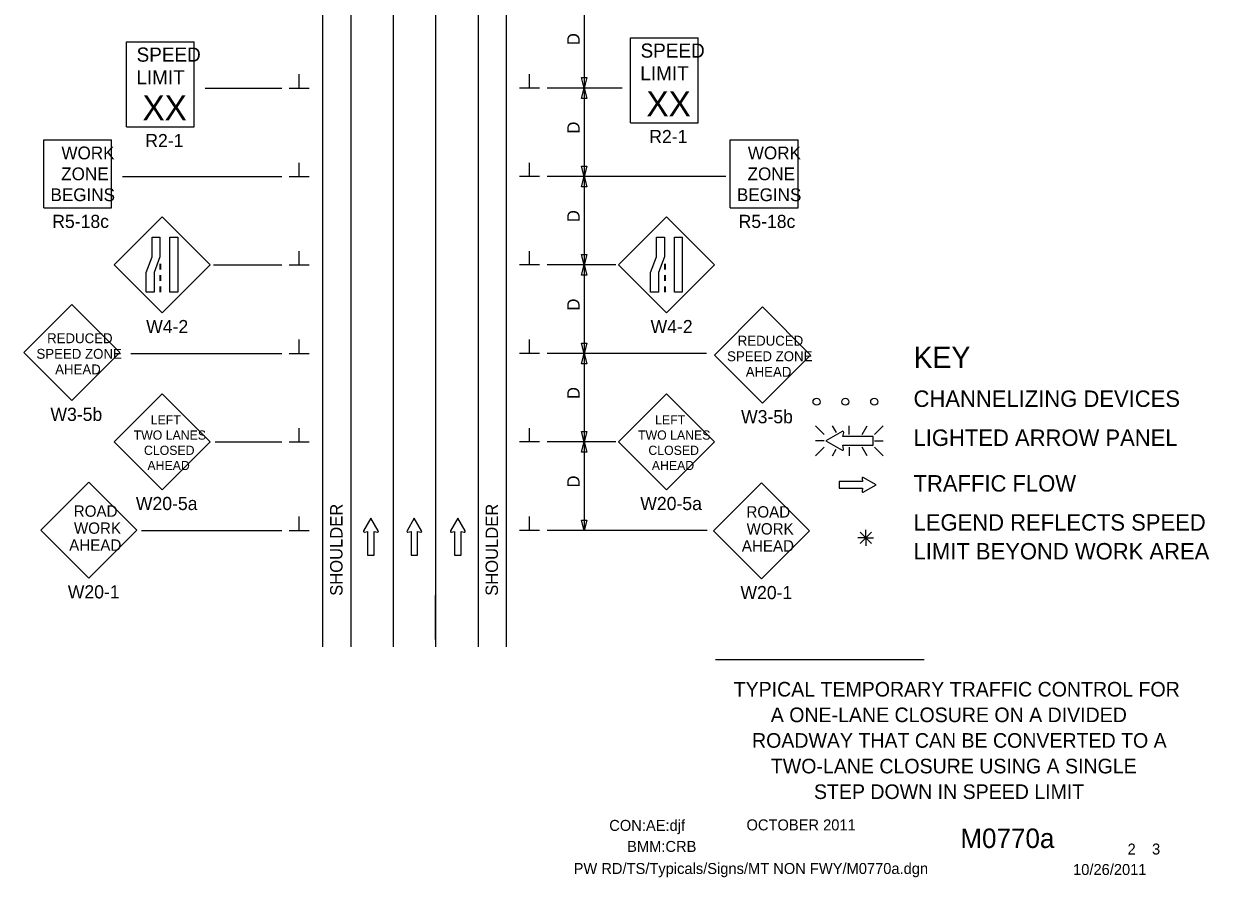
# Model space of a CAD drawing. Extents: x 16744 to 19504, y 5731 to 6974.
# Drawn here: x 17789 to 18459, y 5932 to 6414 of the extents above; entities that cross this region are included whole.
import ezdxf

# ---------------------------------------------------------------- set-up
doc = ezdxf.new("R2010")
doc.units = 0
for name, color, linetype in [('ALI_LEGAL_EX', 7, 'Continuous'), ('BORDER', 7, 'Continuous'), ('BORDER_SIGNAL_WO', 7, 'Continuous'), ('MT_SCRATCH_LEVEL_E', 7, 'Continuous'), ('PAVT_EDGE_EX', 7, 'Continuous'), ('TRAFFIC_SIGNS_PR', 7, 'Continuous'), ('TYPICAL_TEXT_DIMEN_EX', 7, 'Continuous'), ('TYPICAL_TEXT_DIMEN_PR', 7, 'Continuous')]:
    doc.layers.add(name, color=color, linetype=linetype)

msp = doc.modelspace()

# ---------------------------------------------------------------- linework, layer by layer
at = {"layer": 'ALI_LEGAL_EX'}
for p, q in [((17997.5, 6891.16), (17997.5, 6061.98)), ((18021.5, 6891.16), (18021.5, 6061.98)), ((18021.5, 6891.16), (18021.5, 6061.98))]:
    msp.add_line(p, q, dxfattribs=at)
for points in [[(17997.5, 6391.16), (17997.5, 6366.16)], [(18021.5, 6391.16), (18021.5, 6366.16)], [(17997.5, 6291.16), (17997.5, 6266.16)], [(18021.5, 6291.16), (18021.5, 6266.16)], [(17997.5, 6191.16), (17997.5, 6166.16)], [(18021.5, 6191.16), (18021.5, 6166.16)], [(17997.5, 6091.16), (17997.5, 6066.16)], [(18021.5, 6066.16), (18021.5, 6091.16)], [(18021.5, 6091.16), (18021.5, 6066.16)]]:
    msp.add_lwpolyline(points, dxfattribs=at)
at = {"layer": 'BORDER'}
for p, q in [((18179.75, 6055), (18297.75, 6055)), ((18318.25, 6011.25), (18318.25, 6011.25))]:
    msp.add_line(p, q, dxfattribs=at)
at = {"layer": 'MT_SCRATCH_LEVEL_E'}
for p, q in [((18262.92, 6155.51), (18249.66, 6155.51)), ((18249.66, 6155.51), (18249.66, 6151.77)), ((18262.92, 6155.51), (18249.66, 6155.51)), ((18249.66, 6155.51), (18249.66, 6151.77)), ((18262.6, 6157.29), (18262.92, 6155.51)), ((18262.6, 6157.29), (18262.92, 6155.51)), ((18270.53, 6153.66), (18263.29, 6157.77)), ((18270.53, 6153.66), (18263.29, 6157.77)), ((18263.29, 6149.51), (18270.53, 6153.66)), ((18263.29, 6149.51), (18270.53, 6153.66)), ((18249.66, 6151.77), (18262.92, 6151.77)), ((18249.66, 6151.77), (18262.92, 6151.77)), ((18262.92, 6151.77), (18262.6, 6149.99)), ((18262.92, 6151.77), (18262.6, 6149.99)), ((17984.94, 6134.8), (17980.83, 6127.56)), ((17984.94, 6134.8), (17980.83, 6127.56)), ((17989.09, 6127.56), (17984.94, 6134.8)), ((17989.09, 6127.56), (17984.94, 6134.8)), ((18009.47, 6134.8), (18005.36, 6127.56)), ((18009.47, 6134.8), (18005.36, 6127.56)), ((18013.62, 6127.56), (18009.47, 6134.8)), ((18013.62, 6127.56), (18009.47, 6134.8)), ((18034.03, 6134.8), (18029.92, 6127.56)), ((18034.03, 6134.8), (18029.92, 6127.56)), ((18038.18, 6127.56), (18034.03, 6134.8)), ((18038.18, 6127.56), (18034.03, 6134.8)), ((17981.31, 6126.88), (17983.09, 6127.19)), ((17981.31, 6126.88), (17983.09, 6127.19)), ((17983.09, 6127.19), (17983.09, 6113.93)), ((17983.09, 6127.19), (17983.09, 6113.93)), ((17986.83, 6113.93), (17986.83, 6127.19)), ((17986.83, 6127.19), (17988.61, 6126.88)), ((17986.83, 6113.93), (17986.83, 6127.19)), ((17986.83, 6127.19), (17988.61, 6126.88)), ((18005.84, 6126.88), (18007.62, 6127.19)), ((18005.84, 6126.88), (18007.62, 6127.19)), ((18007.62, 6127.19), (18007.62, 6113.93)), ((18007.62, 6127.19), (18007.62, 6113.93)), ((18011.36, 6113.93), (18011.36, 6127.19)), ((18011.36, 6127.19), (18013.14, 6126.88)), ((18011.36, 6113.93), (18011.36, 6127.19)), ((18011.36, 6127.19), (18013.14, 6126.88)), ((18030.4, 6126.88), (18032.18, 6127.19)), ((18030.4, 6126.88), (18032.18, 6127.19)), ((18032.18, 6127.19), (18032.18, 6113.93)), ((18032.18, 6127.19), (18032.18, 6113.93)), ((18035.92, 6113.93), (18035.92, 6127.19)), ((18035.92, 6127.19), (18037.7, 6126.88)), ((18035.92, 6113.93), (18035.92, 6127.19)), ((18035.92, 6127.19), (18037.7, 6126.88)), ((17983.09, 6113.93), (17986.83, 6113.93)), ((17983.09, 6113.93), (17986.83, 6113.93)), ((18007.62, 6113.93), (18011.36, 6113.93)), ((18007.62, 6113.93), (18011.36, 6113.93)), ((18032.18, 6113.93), (18035.92, 6113.93)), ((18032.18, 6113.93), (18035.92, 6113.93))]:
    msp.add_line(p, q, dxfattribs=at)
for centre, start, end in [((18263.06, 6157.36), 60.42484, 189.96381), ((18263.06, 6157.36), 60.42484, 189.96381), ((18263.06, 6149.92), 170.03619, 299.77312), ((18263.06, 6149.92), 170.03619, 299.77312), ((17981.24, 6127.33), 150.42484, 279.96381), ((17981.24, 6127.33), 150.42484, 279.96381), ((17988.68, 6127.34), 260.03619, 29.77312), ((17988.68, 6127.34), 260.03619, 29.77312), ((18005.77, 6127.33), 150.42484, 279.96381), ((18005.77, 6127.33), 150.42484, 279.96381), ((18013.21, 6127.34), 260.03619, 29.77312), ((18013.21, 6127.34), 260.03619, 29.77312), ((18030.33, 6127.33), 150.42484, 279.96381), ((18030.33, 6127.33), 150.42484, 279.96381), ((18037.77, 6127.34), 260.03619, 29.77312), ((18037.77, 6127.34), 260.03619, 29.77312)]:
    msp.add_arc(centre, 0.463, start, end, dxfattribs=at)
at = {"layer": 'PAVT_EDGE_EX'}
for p, q in [((17957.5, 6891.16), (17957.5, 6061.98)), ((17973.5, 6891.16), (17973.5, 6061.98)), ((17973.5, 6891.16), (17973.5, 6061.98)), ((18045.5, 6891.16), (18045.5, 6061.98)), ((18061.5, 6891.16), (18061.5, 6061.98))]:
    msp.add_line(p, q, dxfattribs=at)
at = {"layer": 'TRAFFIC_SIGNS_PR'}
for p, q in [((17846.7, 6403.9), (17885.1, 6403.9)), ((17846.7, 6355.9), (17846.7, 6403.9)), ((17885.1, 6355.9), (17885.1, 6403.9)), ((18131.62, 6406.17), (18170.02, 6406.17)), ((18131.62, 6358.17), (18131.62, 6406.17)), ((18170.02, 6358.17), (18170.02, 6406.17)), ((17846.7, 6355.9), (17885.1, 6355.9)), ((18131.62, 6358.17), (18170.02, 6358.17)), ((17799.96, 6310.22), (17799.96, 6348.61)), ((17799.96, 6348.61), (17838.36, 6348.61)), ((17838.36, 6310.22), (17838.36, 6348.61)), ((18188.03, 6310.22), (18188.03, 6348.61)), ((18188.03, 6348.61), (18226.43, 6348.61)), ((18226.43, 6310.22), (18226.43, 6348.61)), ((17799.96, 6310.22), (17838.36, 6310.22)), ((18188.03, 6310.22), (18226.43, 6310.22)), ((17866.91, 6305.09), (17839.76, 6277.93)), ((17894.06, 6277.93), (17866.91, 6305.09)), ((18152.1, 6305.09), (18124.94, 6277.93)), ((18179.25, 6277.93), (18152.1, 6305.09)), ((17839.76, 6277.93), (17866.91, 6250.78)), ((17865.66, 6278.43), (17865.66, 6275.23)), ((17866.06, 6278.43), (17866.06, 6275.23)), ((17866.91, 6250.78), (17894.06, 6277.93)), ((18124.94, 6277.93), (18152.1, 6250.78)), ((18150.85, 6278.43), (18150.85, 6275.23)), ((18151.25, 6278.43), (18151.25, 6275.23)), ((18152.1, 6250.78), (18179.25, 6277.93)), ((17865.66, 6272.03), (17865.66, 6268.83)), ((17866.06, 6272.03), (17866.06, 6268.83)), ((18150.85, 6272.03), (18150.85, 6268.83)), ((18151.25, 6272.03), (18151.25, 6268.83)), ((17865.66, 6265.63), (17865.66, 6262.43)), ((17866.06, 6265.63), (17866.06, 6262.43)), ((18150.85, 6265.63), (18150.85, 6262.43)), ((18151.25, 6265.63), (18151.25, 6262.43)), ((17815.79, 6255.5), (17788.63, 6228.35)), ((17842.94, 6228.35), (17815.79, 6255.5)), ((18206.26, 6254.15), (18179.11, 6226.99)), ((18233.41, 6226.99), (18206.26, 6254.15)), ((17788.63, 6228.35), (17815.79, 6201.2)), ((17815.79, 6201.2), (17842.94, 6228.35)), ((18179.11, 6226.99), (18206.26, 6199.84)), ((18206.26, 6199.84), (18233.41, 6226.99)), ((17866.91, 6205.1), (17839.76, 6177.95)), ((17894.06, 6177.95), (17866.91, 6205.1)), ((18152.1, 6205.1), (18124.94, 6177.95)), ((18179.25, 6177.95), (18152.1, 6205.1)), ((18236.34, 6187.04), (18241.27, 6182.11)), ((18248.1, 6183.22), (18245.89, 6187.05)), ((18255.42, 6182.11), (18255.42, 6187.05)), ((18262.66, 6182.11), (18265.51, 6187.05)), ((18269.57, 6182.11), (18274.51, 6187.05)), ((17839.76, 6177.95), (17866.91, 6150.8)), ((17866.91, 6150.8), (17894.06, 6177.95)), ((18124.94, 6177.95), (18152.1, 6150.8)), ((18152.1, 6150.8), (18179.25, 6177.95)), ((18241.27, 6178.56), (18236.34, 6178.56)), ((18236.34, 6170.07), (18241.27, 6175)), ((18245.85, 6170.06), (18247.96, 6173.73)), ((18255.42, 6175), (18255.42, 6170.06)), ((18265.55, 6170.06), (18262.7, 6175)), ((18269.57, 6178.56), (18274.51, 6178.56)), ((18269.57, 6175), (18274.51, 6170.06)), ((17825.39, 6155.19), (17798.24, 6128.04)), ((17852.54, 6128.04), (17825.39, 6155.19)), ((18205.69, 6154.77), (18178.54, 6127.61)), ((18232.85, 6127.61), (18205.69, 6154.77)), ((17798.24, 6128.04), (17825.39, 6100.88)), ((17825.39, 6100.88), (17852.54, 6128.04)), ((18178.54, 6127.61), (18205.69, 6100.46)), ((18205.69, 6100.46), (18232.85, 6127.61))]:
    msp.add_line(p, q, dxfattribs=at)
for points in [[(17865.66, 6293.67), (17865.66, 6282.49), (17862.32, 6273.61), (17862.32, 6262.43), (17857.82, 6262.43), (17857.82, 6273.61), (17861.17, 6282.49), (17861.17, 6293.67)], [(17875.8, 6293.67), (17875.8, 6262.43), (17871.31, 6262.43), (17871.31, 6293.67)], [(18150.85, 6293.67), (18150.85, 6282.49), (18147.51, 6273.61), (18147.51, 6262.43), (18143.01, 6262.43), (18143.01, 6273.61), (18146.36, 6282.49), (18146.36, 6293.67)], [(18160.99, 6293.67), (18160.99, 6262.43), (18156.49, 6262.43), (18156.49, 6293.67)]]:
    msp.add_lwpolyline(points, close=True, dxfattribs=at)
for points in [[(18251.35, 6183.83), (18242.06, 6178.56), (18251.35, 6173.23)], [(18252.22, 6173.86), (18251.82, 6176.13), (18268.84, 6176.13), (18268.84, 6180.93), (18251.82, 6180.93), (18252.23, 6183.21)]]:
    msp.add_lwpolyline(points, dxfattribs=at)
for centre in [(18236.9, 6200.59), (18253.2, 6200.59), (18269.5, 6200.59)]:
    msp.add_circle(centre, 2, dxfattribs=at)
for centre, radius, start, end in [((18251.64, 6183.31), 0.598, 350.73078, 118.89165), ((18251.63, 6173.76), 0.597, 241.48329, 9.95933)]:
    msp.add_arc(centre, radius, start, end, dxfattribs=at)
at = {"layer": 'TYPICAL_TEXT_DIMEN_PR'}
for p, q in [((18105.5, 6425.88), (18105.5, 6377.89)), ((17944.38, 6377.89), (17944.38, 6385.67)), ((18074.63, 6377.89), (18074.63, 6385.67)), ((18105.5, 6377.89), (18103.93, 6383.75)), ((18103.93, 6383.75), (18105.5, 6383.75)), ((18105.5, 6383.75), (18107.07, 6383.75)), ((18107.07, 6383.75), (18105.5, 6377.89)), ((17891.24, 6377.89), (17934.5, 6377.89)), ((17938.75, 6377.89), (17950, 6377.89)), ((18080.25, 6377.89), (18069, 6377.89)), ((18126.94, 6377.89), (18084.5, 6377.89)), ((18103.93, 6372.03), (18105.5, 6377.89)), ((18105.5, 6377.89), (18105.5, 6327.89)), ((18105.5, 6377.89), (18107.07, 6372.03)), ((18105.5, 6372.03), (18103.93, 6372.03)), ((18107.07, 6372.03), (18105.5, 6372.03)), ((17944.38, 6327.89), (17944.38, 6335.67)), ((18074.63, 6327.89), (18074.63, 6335.67)), ((17844.42, 6327.89), (17934.5, 6327.89)), ((17938.75, 6327.89), (17950, 6327.89)), ((18080.25, 6327.89), (18069, 6327.89)), ((18185.52, 6327.89), (18084.5, 6327.89)), ((18105.5, 6327.89), (18103.93, 6333.75)), ((18103.93, 6333.75), (18105.5, 6333.75)), ((18103.93, 6322.03), (18105.5, 6327.89)), ((18105.5, 6333.75), (18107.07, 6333.75)), ((18107.07, 6333.75), (18105.5, 6327.89)), ((18105.5, 6327.89), (18107.07, 6322.03)), ((18105.5, 6327.89), (18105.5, 6277.89)), ((18105.5, 6322.03), (18103.93, 6322.03)), ((18107.07, 6322.03), (18105.5, 6322.03)), ((17944.38, 6277.89), (17944.38, 6285.67)), ((18074.63, 6277.89), (18074.63, 6285.67)), ((18105.5, 6277.89), (18103.93, 6283.75)), ((18103.93, 6283.75), (18105.5, 6283.75)), ((18105.5, 6283.75), (18107.07, 6283.75)), ((18107.07, 6283.75), (18105.5, 6277.89)), ((17895.99, 6277.89), (17934.5, 6277.89)), ((17938.75, 6277.89), (17950, 6277.89)), ((18080.25, 6277.89), (18069, 6277.89)), ((18123.5, 6277.89), (18084.5, 6277.89)), ((18103.93, 6272.03), (18105.5, 6277.89)), ((18105.5, 6277.89), (18105.5, 6227.89)), ((18105.5, 6277.89), (18107.07, 6272.03)), ((18105.5, 6272.03), (18103.93, 6272.03)), ((18107.07, 6272.03), (18105.5, 6272.03)), ((17944.38, 6227.89), (17944.38, 6235.67)), ((18074.63, 6227.89), (18074.63, 6235.67)), ((17849.12, 6227.89), (17934.5, 6227.89)), ((17938.75, 6227.89), (17950, 6227.89)), ((18080.25, 6227.89), (18069, 6227.89)), ((18174.62, 6227.89), (18084.5, 6227.89)), ((18105.5, 6227.89), (18103.93, 6233.75)), ((18103.93, 6233.75), (18105.5, 6233.75)), ((18103.93, 6222.03), (18105.5, 6227.89)), ((18105.5, 6233.75), (18107.07, 6233.75)), ((18107.07, 6233.75), (18105.5, 6227.89)), ((18105.5, 6227.89), (18105.5, 6177.89)), ((18105.5, 6227.89), (18107.07, 6222.03)), ((18105.5, 6222.03), (18103.93, 6222.03)), ((18107.07, 6222.03), (18105.5, 6222.03)), ((17944.38, 6177.89), (17944.38, 6185.67)), ((18074.63, 6177.89), (18074.63, 6185.67)), ((18105.5, 6177.89), (18103.93, 6183.75)), ((18103.93, 6183.75), (18105.5, 6183.75)), ((18105.5, 6183.75), (18107.07, 6183.75)), ((18107.07, 6183.75), (18105.5, 6177.89)), ((17896.93, 6177.89), (17934.5, 6177.89)), ((17938.75, 6177.89), (17950, 6177.89)), ((18080.25, 6177.89), (18069, 6177.89)), ((18123.5, 6177.89), (18084.5, 6177.89)), ((18103.93, 6172.03), (18105.5, 6177.89)), ((18105.5, 6177.89), (18105.5, 6127.89)), ((18105.5, 6177.89), (18107.07, 6172.03)), ((18105.5, 6172.03), (18103.93, 6172.03)), ((18107.07, 6172.03), (18105.5, 6172.03)), ((17944.38, 6127.89), (17944.38, 6135.67)), ((18074.63, 6127.89), (18074.63, 6135.67)), ((18105.5, 6127.89), (18103.93, 6133.75)), ((18103.93, 6133.75), (18105.5, 6133.75)), ((18105.5, 6133.75), (18107.07, 6133.75)), ((18107.07, 6133.75), (18105.5, 6127.89)), ((17855.21, 6127.89), (17934.5, 6127.89)), ((17938.75, 6127.89), (17950, 6127.89)), ((18080.25, 6127.89), (18069, 6127.89)), ((18175.09, 6127.89), (18084.5, 6127.89)), ((18261.49, 6126.9), (18267.87, 6120.53)), ((18267.87, 6126.9), (18261.49, 6120.53)), ((18264.68, 6123.72), (18264.68, 6128.17)), ((18264.68, 6123.72), (18260.15, 6123.72)), ((18264.68, 6123.72), (18267.87, 6123.72)), ((18264.68, 6123.72), (18269.15, 6123.72)), ((18264.68, 6123.72), (18264.68, 6119.22))]:
    msp.add_line(p, q, dxfattribs=at)

# ---------------------------------------------------------------- texts
at = {"layer": 'BORDER'}
for s, p in [('TYPICAL TEMPORARY TRAFFIC CONTROL FOR', (18190.04, 6033.99)), ('A ONE-LANE CLOSURE ON A DIVIDED', (18211.02, 6019.51)), ('ROADWAY THAT CAN BE CONVERTED TO A', (18200.42, 6005.04)), ('TWO-LANE CLOSURE USING A SINGLE', (18211.06, 5990.56)), ('STEP DOWN IN SPEED LIMIT', (18235.42, 5976.08))]:
    msp.add_text(s, height=8.2598, dxfattribs=at).set_placement(p)
at = {"layer": 'BORDER_SIGNAL_WO'}
for s, height, p in [('CON:AE:djf', 6.2, (18119.69, 5958.06)), ('    OCTOBER 2011    ', 6.2, (18188.08, 5958.34)), ('    M0770a   ', 11, (18301.86, 5948.38)), ('BMM:CRB   ', 6.2, (18129.81, 5946.17)), (' 2    3 ', 6.2, (18410.45, 5944.7)), ('PW RD/TS/Typicals/Signs/MT NON FWY/M0770a.dgn    ', 6.2, (18099.55, 5933.71)), ('10/26/2011    ', 6.2, (18381.93, 5933.13))]:
    msp.add_text(s, height=height, dxfattribs=at).set_placement(p)
at = {"layer": 'TRAFFIC_SIGNS_PR'}
for s, height, p in [('SPEED', 8, (18137.39, 6395.03)), ('SPEED', 8, (17852.47, 6392.76)), ('LIMIT', 8, (18137.23, 6382.23)), ('LIMIT', 8, (17852.31, 6379.96)), ('XX', 14.031, (18140.73, 6361.93)), ('XX', 14.031, (17855.81, 6359.65)), ('R2-1', 7.44, (17857.38, 6344.46)), ('R2-1', 7.44, (18142.3, 6346.73)), ('WORK', 7.217, (17809.96, 6337.58)), ('WORK', 7.217, (18198.03, 6337.58)), ('ZONE', 7.217, (17809.84, 6325.77)), ('ZONE', 7.217, (18197.91, 6325.77)), ('BEGINS', 7.217, (17803.77, 6313.96)), ('BEGINS', 7.217, (18191.84, 6313.96)), ('R5-18c', 7.44, (17804.77, 6298.78)), ('R5-18c', 7.44, (18192.84, 6298.78)), ('W4-2', 7.44, (17857.87, 6239.34)), ('W4-2', 7.44, (18143.06, 6239.34)), ('REDUCED', 5.6, (17801.85, 6233.66)), ('REDUCED', 5.6, (18192.32, 6232.3)), ('SPEED ZONE', 5.6, (17795.84, 6224.86)), ('SPEED ZONE', 5.6, (18186.31, 6223.5)), ('AHEAD', 5.6, (17806.4, 6216.06)), ('AHEAD', 5.6, (18196.87, 6214.7)), ('W3-5b', 7.44, (17803.74, 6189.76)), ('W3-5b', 7.44, (18194.21, 6188.4)), ('LEFT', 5.2, (17860.45, 6187.74)), ('LEFT', 5.2, (18145.63, 6187.74)), ('TWO LANES', 5.2, (17850.77, 6179.14)), ('TWO LANES', 5.2, (18135.96, 6179.14)), ('CLOSED', 5.2, (17856.62, 6170.54)), ('CLOSED', 5.2, (18141.81, 6170.54)), ('AHEAD', 5.2, (17858.57, 6161.94)), ('AHEAD', 5.2, (18143.75, 6161.94)), ('W20-5a', 7.44, (17852.05, 6139.36)), ('W20-5a', 7.44, (18137.24, 6139.36)), ('ROAD', 6.4, (17816.93, 6135.57)), ('ROAD', 6.4, (18197.24, 6135.15)), ('WORK', 6.4, (17817.04, 6125.97)), ('WORK', 6.4, (18197.34, 6125.55)), ('AHEAD', 6.4, (17814.35, 6116.37)), ('AHEAD', 6.4, (18194.65, 6115.95)), ('W20-1', 7.44, (17813.56, 6089.44)), ('W20-1', 7.44, (18193.86, 6089.02))]:
    msp.add_text(s, height=height, dxfattribs=at).set_placement(p)
at = {"layer": 'TYPICAL_TEXT_DIMEN_EX'}
for s, height, p in [('KEY', 12, (18291.74, 6219.69)), ('CHANNELIZING DEVICES', 9.3, (18291.74, 6197.65)), ('LIGHTED ARROW PANEL', 9.3, (18291.74, 6175.6)), ('TRAFFIC FLOW', 9.3, (18291.74, 6149.8)), ('LEGEND REFLECTS SPEED', 9.3, (18291.74, 6127.74)), ('LIMIT BEYOND WORK AREA', 9.3, (18291.74, 6111.44))]:
    msp.add_text(s, height=height, dxfattribs=at).set_placement(p)
at = {"layer": 'TYPICAL_TEXT_DIMEN_PR'}
for s, p in [('D', (18102.94, 6402.11)), ('D', (18102.94, 6352.11)), ('D', (18102.94, 6302.11)), ('D', (18102.94, 6252.11)), ('D', (18102.94, 6202.11)), ('D', (18102.94, 6152.11)), ('SHOULDER', (17968.88, 6090.91)), ('SHOULDER', (18056.78, 6090.91))]:
    msp.add_text(s, height=7, rotation=90, dxfattribs=at).set_placement(p)

doc.saveas('drawing.dxf')
